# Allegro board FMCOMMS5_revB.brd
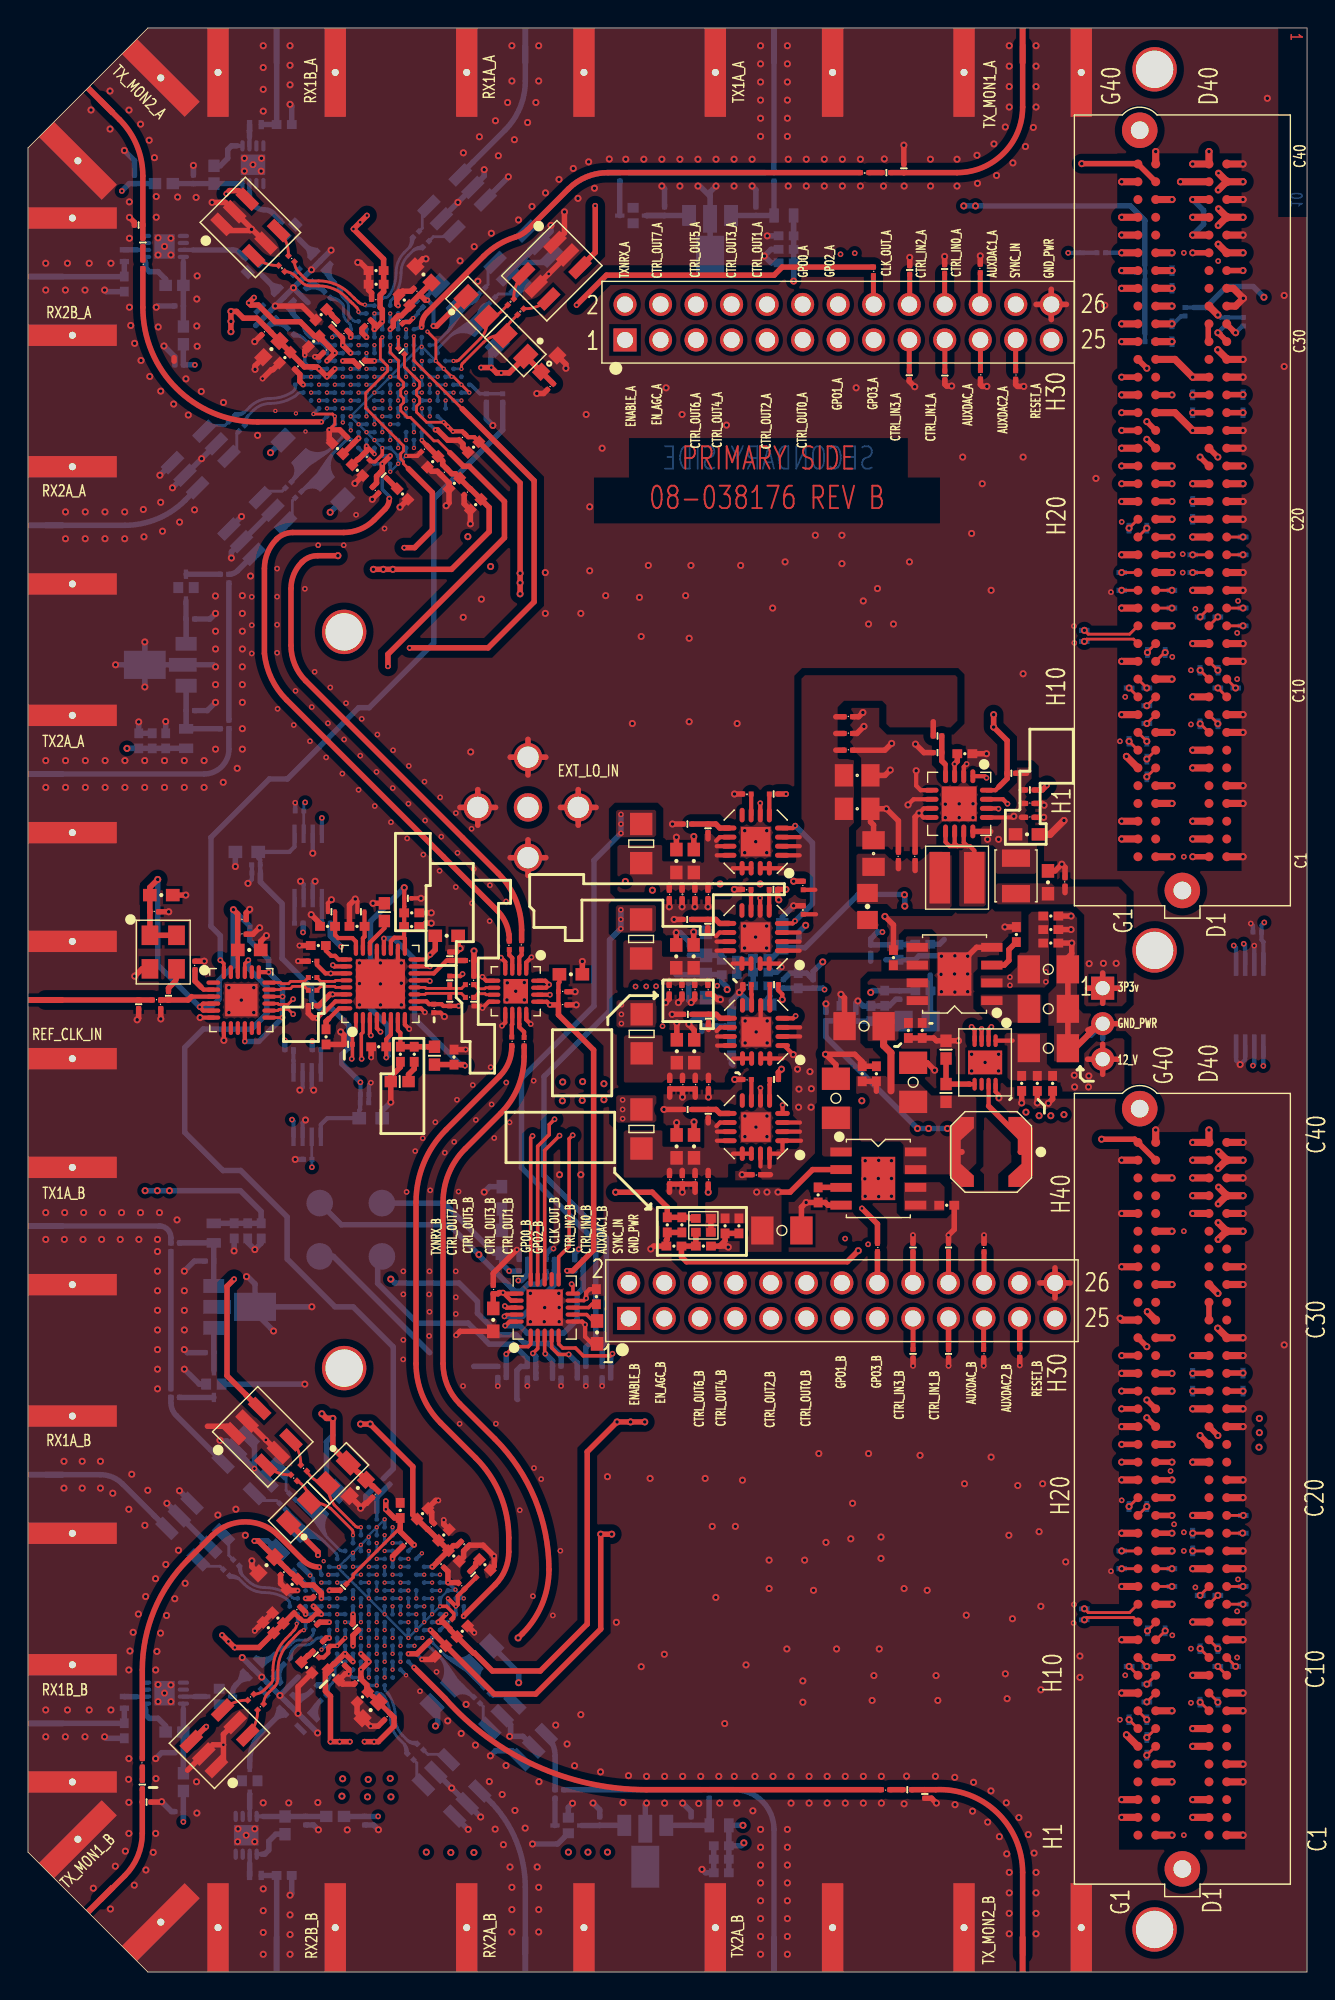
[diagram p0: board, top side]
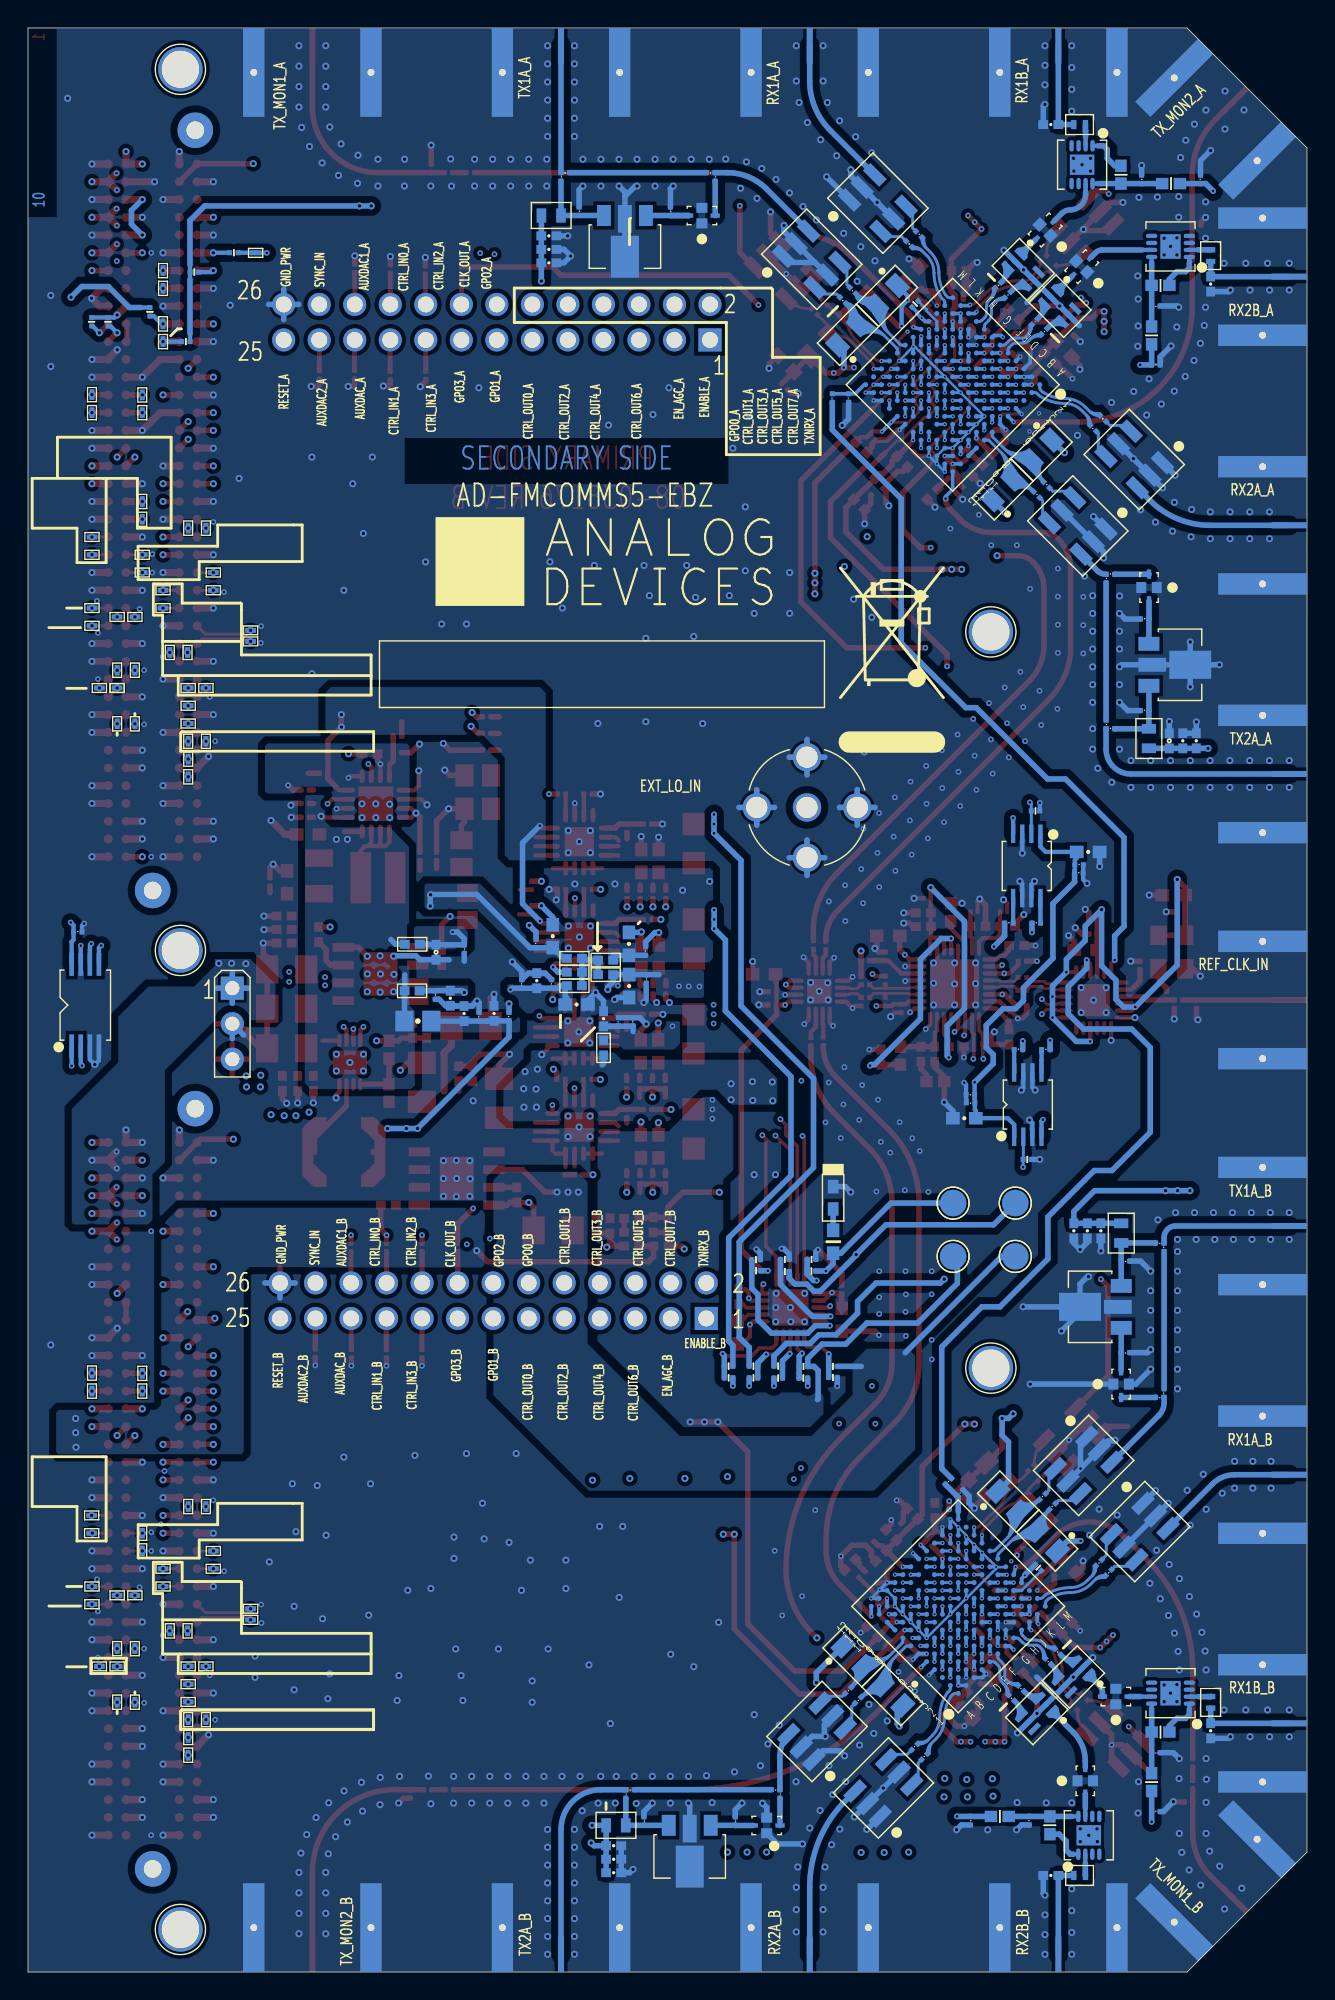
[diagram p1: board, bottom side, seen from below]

Outline 91.45 x 139 mm; copper layers: TOP, L2_GND, L3_PWR, L4_GND, L5_SIG, L6_SIG, L7_GND, L8_PWR, L9_GND, BOTTOM. Coordinates in mm from the lower left corner of the outline.
Outline path: 0,130.42 0,8.57 8.57,0 91.45,0 91.45,139 8.57,139 0,130.42

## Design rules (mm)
net group DIFFPAIR15: nets RX_D5_N_A RX_D5_P_A
net group DIFFPAIR16: nets RX_D2_N_A RX_D2_P_A
net group DIFFPAIR17: nets RX_D0_N_A RX_D0_P_A
net group DIFFPAIR18: nets DATA_CLK_N_A DATA_CLK_P_A
net group DIFFPAIR19: nets RX_D1_N_A RX_D1_P_A
net group DIFFPAIR20: nets RX_FRAME_N_A RX_FRAME_P_A
net group DIFFPAIR21: nets RX_D3_N_A RX_D3_P_A
net group DIFFPAIR22: nets RX_D4_N_A RX_D4_P_A
net group DIFFPAIR23: nets RX_D5_N_B RX_D5_P_B
net group DIFFPAIR24: nets RX_D2_N_B RX_D2_P_B
net group DIFFPAIR25: nets RX_D0_N_B RX_D0_P_B
net group DIFFPAIR26: nets DATA_CLK_N_B DATA_CLK_P_B
net group DIFFPAIR27: nets RX_D1_N_B RX_D1_P_B
net group DIFFPAIR28: nets RX_FRAME_N_B RX_FRAME_P_B
net group DIFFPAIR29: nets RX_D3_N_B RX_D3_P_B
net group DIFFPAIR30: nets RX_D4_N_B RX_D4_P_B
net group DIFFPAIR31: nets FB_CLK_N_A FB_CLK_P_A
net group DIFFPAIR32: nets TX_D4_N_A TX_D4_P_A
net group DIFFPAIR33: nets TX_D0_N_A TX_D0_P_A
net group DIFFPAIR34: nets TX_D2_N_A TX_D2_P_A
net group DIFFPAIR35: nets TX_FRAME_N_A TX_FRAME_P_A
net group DIFFPAIR36: nets TX_D3_N_A TX_D3_P_A
net group DIFFPAIR37: nets TX_D1_N_A TX_D1_P_A
net group DIFFPAIR38: nets TX_D5_N_A TX_D5_P_A
net group DIFFPAIR39: nets TX_D5_N_B TX_D5_P_B
net group DIFFPAIR40: nets TX_D1_N_B TX_D1_P_B
net group DIFFPAIR41: nets TX_D2_N_B TX_D2_P_B
net group DIFFPAIR42: nets FB_CLK_N_B FB_CLK_P_B
net group DIFFPAIR43: nets TX_D3_N_B TX_D3_P_B
net group DIFFPAIR44: nets TX_FRAME_N_B TX_FRAME_P_B
net group DIFFPAIR45: nets TX_D4_N_B TX_D4_P_B
net group DIFFPAIR46: nets TX_D0_N_B TX_D0_P_B
net group DIFFPAIR47: nets REF_CLK_FMC_N REF_CLK_FMC_P
net group DIFFPAIR48: nets CAL_SW_1 CAL_SW_2
net group DIFFPAIR49: nets 5355_REF_N 5355_REF_P
net group DIFFPAIR50: nets UNNAMED_5_ADCLK846_I21_OUT2 UNNAMED_5_ADCLK846_I21_OUT2N
net group DIFFPAIR51: nets TX1B_N_A TX1B_P_A
net group DIFFPAIR52: nets RX1C_N_A RX1C_P_A
net group DIFFPAIR53: nets TX2A_N_B TX2A_P_B
net group DIFFPAIR54: nets RX2A_N_B RX2A_P_B
net group DIFFPAIR55: nets TX1A_N_B TX1A_P_B
net group DIFFPAIR56: nets RX1A_N_B RX1A_P_B
net group DIFFPAIR57: nets RX2B_N_A RX2B_P_A
net group DIFFPAIR58: nets RX1B_N_A RX1B_P_A
net group DIFFPAIR59: nets RX1B_N_B RX1B_P_B
net group DIFFPAIR60: nets RX2B_N_B RX2B_P_B
net group DIFFPAIR61: nets TX1B_N_B TX1B_P_B
net group DIFFPAIR62: nets RX1C_N_B RX1C_P_B
net group DIFFPAIR63: nets 13617_IN_N 13617_IN_P
net group DIFFPAIR64: nets 5355_RFOUT_N 5355_RFOUT_P
net group SINGLE-ENDED: nets RX1A_N_A RX1A_P_A RX2A_N_A RX2A_P_A SYNC_IN TX1A_N_A TX1A_P_A TX2A_N_A TX2A_P_A

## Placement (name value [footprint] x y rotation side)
C101  1000pF  [C0201]  59.82 128.66 180 top
C102  1000pF  [C0201]  8.21 122.11 270 top
C103  1uF  [C0402]  7.92 88.03 90 bottom
C104  1000pF  [C0201]  24.85 105.96 135 top
C105  1uF  [C0402]  26.78 105.68 315 top
C106  18pF  [C0201]  28.45 123.54 225 bottom
C107  18pF  [C0201]  27.75 124.24 225 bottom
C108  18pF  [C0201]  14.59 111.08 45 bottom
C109  18pF  [C0201]  15.29 110.38 45 bottom
C110  18pF  [C0201]  14.37 99.63 270 bottom
C111  18pF  [C0201]  14.37 89.2 270 bottom
C112  1200pF  [C0402]  9.85 88.03 270 bottom
C113  68pF  [C0402]  8.88 88.03 270 bottom
C114  18pF  [C0201]  11.61 96.74 180 bottom
C115  18pF  [C0201]  11.61 90.19 180 bottom
C116  1000pF  [C0201]  22.61 117.13 45 top
C117  1uF  [C0402]  20.96 118.5 225 top
C118  1000pF  [C0201]  37.35 113.35 45 top
C119  10UF  [C0603]  37.27 115 45 top
C120  1000pF  [C0201]  16.92 117.26 45 top
C121  10UF  [C0603]  17.41 116.04 225 top
C122  18pF  [C0201]  33.18 119.53 45 bottom
C123  18pF  [C0201]  32.48 120.23 45 bottom
C124  18pF  [C0201]  18.63 106.33 225 bottom
C125  18pF  [C0201]  19.33 105.63 225 bottom
C126  18pF  [C0201]  18.84 122.5 315 top
C127  18pF  [C0201]  18.14 121.8 315 top
C128  18pF  [C0201]  22.08 120.61 315 bottom
C129  18pF  [C0201]  21.4 119.93 315 bottom
C130  18pF  [C0201]  19.47 118 315 bottom
C131  18pF  [C0201]  18.78 117.31 315 bottom
C132  18pF  [C0201]  34.52 119.41 45 top
C133  18pF  [C0201]  35.22 118.71 45 top
C134  1000pF  [C0201]  27.8 120.15 315 top
C135  10UF  [C0603]  28.28 121.37 135 top
C136  18pF  [C0201]  42.63 128.66 0 bottom
C137  18pF  [C0201]  53.04 128.66 0 bottom
C138  0.1uF  [C0201]  42.32 128.35 270 bottom
C139  0.1uF  [C0201]  53.34 128.35 270 bottom
C140  0.1uF  [C0201]  14.06 99.93 180 bottom
C142  0.1uF  [C0201]  60.45 121.6 270 top
C143  0.1uF  [C0201]  68.1 114.2 270 top
C144  0.1uF  [C0201]  68.09 121.81 90 top
C145  0.1uF  [C0201]  70.62 114.19 270 top
C146  0.75pF  [C0402]  18.32 132.09 180 bottom
C147  1000pF  [C0201]  11.83 128.18 270 bottom
C148  0.1uF  [C0201]  7.62 128.18 90 bottom
C149  1000pF  [C0201]  10.81 119.12 0 bottom
C150  0.1uF  [C0201]  10.81 114.91 180 bottom
C151  0.75pF  [C0402]  6.89 120.69 90 bottom
C152  1uF  [C0402]  54.21 124.14 180 bottom
C153  1200pF  [C0402]  54.21 122.2 0 bottom
C154  68pF  [C0402]  54.21 123.17 0 bottom
C155  18pF  [C0201]  52.05 125.9 270 bottom
C156  18pF  [C0201]  45.52 125.9 270 bottom
C162  0.1uF  [C0201]  14.06 88.9 180 bottom
C165  39pF  [C0201]  33.94 112.54 90 bottom
C166  18pF  [C0201]  32.78 112.54 90 bottom
C201  1000pF  [C0201]  8.17 14.96 90 top
C202  1000pF  [C0201]  61.32 13.04 180 top
C203  1uF  [C0402]  49.57 8.07 180 bottom
C204  1000pF  [C0201]  31 27.6 315 top
C205  1uF  [C0402]  32.67 29.12 315 top
C206  18pF  [C0201]  27.35 15.4 135 bottom
C207  18pF  [C0201]  28.05 16.1 135 bottom
C208  18pF  [C0201]  14.89 29.26 315 bottom
C209  18pF  [C0201]  14.19 28.56 315 bottom
C210  18pF  [C0201]  37.99 13.04 0 bottom
C211  18pF  [C0201]  48.4 13.04 0 bottom
C212  1200pF  [C0402]  49.57 7.1 0 bottom
C213  68pF  [C0402]  49.57 9.03 0 bottom
C214  18pF  [C0201]  40.89 10.79 270 bottom
C215  18pF  [C0201]  47.41 10.79 270 bottom
C216  1000pF  [C0201]  21.3 23.42 135 top
C217  1uF  [C0402]  19.93 21.77 315 top
C218  1000pF  [C0201]  24.84 34.14 45 top
C219  10UF  [C0603]  23.59 34.61 225 top
C220  1000pF  [C0201]  25.69 18.24 45 top
C221  10UF  [C0603]  24.5 18.73 225 top
C222  18pF  [C0201]  18.91 33.99 135 bottom
C223  18pF  [C0201]  18.2 33.29 135 bottom
C224  18pF  [C0201]  32.1 19.44 315 bottom
C225  18pF  [C0201]  32.8 20.14 315 bottom
C226  18pF  [C0201]  15.93 19.65 45 top
C227  18pF  [C0201]  16.63 18.95 45 top
C228  18pF  [C0201]  17.82 22.89 45 bottom
C229  18pF  [C0201]  18.5 22.21 45 bottom
C230  18pF  [C0201]  20.44 20.28 45 bottom
C231  18pF  [C0201]  21.12 19.6 45 bottom
C232  18pF  [C0201]  19.02 35.33 135 top
C233  18pF  [C0201]  19.72 36.03 135 top
C234  1000pF  [C0201]  28.82 31.86 225 top
C235  10UF  [C0603]  17.06 29.09 225 top
C236  18pF  [C0201]  10.22 41.4 90 bottom
C237  18pF  [C0201]  10.22 51.82 90 bottom
C238  0.1uF  [C0201]  10.53 41.09 0 bottom
C239  0.1uF  [C0201]  10.53 52.13 0 bottom
C240  0.1uF  [C0201]  37.69 12.73 270 bottom
C242  0.1uF  [C0201]  60.74 51.8 270 top
C243  0.1uF  [C0201]  68.33 44.21 270 top
C244  0.1uF  [C0201]  68.36 51.8 90 top
C245  0.1uF  [C0201]  70.91 44.25 270 top
C246  0.75pF  [C0402]  6.89 17.25 90 bottom
C247  1000pF  [C0201]  10.81 15.68 0 bottom
C248  0.1uF  [C0201]  10.81 11.47 180 bottom
C249  1000pF  [C0201]  19.86 10.82 90 bottom
C250  0.1uF  [C0201]  24.07 10.82 270 bottom
C251  0.75pF  [C0402]  18.32 6.91 180 bottom
C252  1uF  [C0402]  15.71 52.99 270 bottom
C253  1200pF  [C0402]  16.67 52.99 90 bottom
C254  68pF  [C0402]  14.74 52.99 90 bottom
C255  18pF  [C0201]  12.98 50.83 0 bottom
C256  18pF  [C0201]  12.98 44.29 0 bottom
C262  0.1uF  [C0201]  48.71 12.73 270 bottom
C265  39pF  [C0201]  25.65 35.09 315 bottom
C266  18pF  [C0201]  24.82 34.26 315 bottom
C301  0.1uF  [C0201]  9.19 69.5 0 top
C302  0.01UF  [C0201]  11.94 71.97 90 top
C303  10UF  [C0603]  15.82 73.08 0 top
C304  0.1uF  [C0201]  15.3 74.21 0 top
C305  0.1uF  [C0201]  15.3 75.25 0 top
C306  10UF  [C0603]  29.94 74.09 0 top
C307  0.1uF  [C0201]  20.35 72.28 180 top
C308  0.1uF  [C0201]  29.01 68.9 270 top
C309  0.1UF  [C0402]  27.43 74.75 180 top
C310  0.1uF  [C0201]  87.89 74.36 180 bottom
C311  0.1uF  [C0201]  33.27 48.8 270 top
C312  10UF  [C0603]  33.27 46.63 270 top
C313  1uF  [C0402]  40.64 48.29 90 top
C314  10UF  [C0603]  40.69 45.73 270 top
C317  1uF  [C0402]  25.08 66.15 0 top
C318  0.01UF  [C0201]  20.35 71.11 0 top
C319  0.01UF  [C0201]  20.35 70.19 0 top
C320  0.1UF  [C0402]  27.44 75.73 180 top
C321  0.1UF  [C0402]  23.53 74.76 0 top
C322  0.1UF  [C0402]  21.42 74.76 0 top
C323  10pF  [C0201-2]  27.16 76.77 180 top
C324  10pF  [C0201-2]  23.81 75.81 0 top
C325  10pF  [C0201-2]  21.7 75.81 0 top
C326  0.1UF  [C0402]  21.31 66.86 90 top
C327  0.1UF  [C0402]  20.76 73.39 0 top
C328  2700PF  [C0402]  26.63 65.62 90 top
C329  39000pF  [C0402]  27.62 65.62 90 top
C330  1200pF  [C0402]  30.46 65.42 270 top
C331  18pF  [C0201]  31.58 69.68 0 top
C332  18pF  [C0201]  31.58 70.6 0 top
C333  10UF  [C0603]  38.82 71.34 0 top
C334  0.1uF  [C0201]  38.23 70.09 0 top
C335  0.1uF  [C0201]  38.23 69.15 0 top
C336  18pF  [C0201]  35.3 73.44 90 top
C337  18pF  [C0201]  34.41 73.41 90 top
C338  18pF  [C0201]  35.47 66.51 270 top
C339  18pF  [C0201]  34.59 66.55 270 top
C340  10UF  [C0603]  15.65 80.09 180 bottom
C341  0.1uF  [C0201]  16.3 79.17 180 bottom
C342  0.1uF  [C0201]  16.31 78.58 180 bottom
C343  10UF  [C0603]  24.5 61.05 0 bottom
C344  0.1uF  [C0201]  24.07 62.75 0 bottom
C345  0.1uF  [C0201]  24.06 62.15 0 bottom
C346  10UF  [C0603]  9.53 77 0 top
C347  0.1uF  [C0201]  9.02 75.81 0 top
C348  18pF  [C0201]  9.5 69.19 90 top
C349  18pF  [C0201]  19.36 74.99 180 bottom
C350  18pF  [C0201]  21.32 74.99 180 bottom
C351  18pF  [C0201]  20.63 65.95 180 bottom
C352  18pF  [C0201]  18.68 65.95 180 bottom
C353  18pF  [C0201]  31.59 72.32 180 top
C390  18pF  [C0201]  31.88 70.9 90 top
C501  0.1uF  [C0201]  74.15 77.94 90 top
C502  10UF  [C0603]  72.93 77.91 90 top
C503  10UF  [C0603]  71.43 81.34 0 top
C504  0.1uF  [C0201]  71.64 82.56 0 top
C505  0.1uF  [C0201]  71.64 83.55 0 top
C510  1uF  [C0402]  58.13 68.54 90 bottom
C511  0.01UF  [C0201]  57.06 68.31 90 bottom
C512  0.01UF  [C0201]  59.2 68.3 90 bottom
C513  1uF  [C0402]  60.27 68.53 90 bottom
C514  0.1uF  [C0201]  46.78 56.64 270 top
C515  0.01UF  [C0201]  22.44 22.13 315 top
C516  1uF  [C0402]  21.83 21.24 315 top
C517  1uF  [C0402]  17.18 24.62 135 top
C518  1uF  [C0402]  62.28 72.92 270 bottom
C519  0.01UF  [C0201]  60.26 73.14 270 bottom
C520  0.01UF  [C0201]  23.05 109.51 135 top
C521  1uF  [C0402]  22.13 108.93 135 top
C522  1uF  [C0402]  61.26 69.63 270 bottom
C523  0.01UF  [C0201]  62.33 69.86 270 bottom
C524  0.01UF  [C0201]  28.92 23.86 225 top
C525  1uF  [C0402]  29.5 22.94 225 top
C530  10uF  [C1206H71]  72.96 66.05 180 top
C531  0.1UF  [C0402]  71.05 63.54 90 top
C532  0.1UF  [C0402]  72.17 63.54 90 top
C533  0.1UF  [C0402]  73.26 63.54 90 top
C534  10uF  [C1206H71]  63.29 63.61 270 top
C535  0.1UF  [C0402]  60.66 64.22 270 top
C536  0.1UF  [C0402]  59.65 64.22 270 top
C537  10uF  [C1206H71]  57.77 62.47 90 top
C538  1uF  [C0402]  56.5 55.56 90 top
C539  1uF  [C0402]  65.69 54.83 180 top
C540  10uF  [C1206H71]  53.91 53.02 180 top
C541  0.1UF  [C0402]  49.84 53.35 90 top
C542  0.1UF  [C0402]  50.83 53.35 90 top
C543  0.1UF  [C0402]  46.75 53.42 90 top
C544  1uF  [C0402]  45.71 53.42 90 top
C545  0.01UF  [C0201]  30.11 25.03 45 top
C546  1uF  [C0402]  17.87 25.31 135 top
C547  0.1UF  [C0402]  48.29 51.9 180 top
C548  1uF  [C0402]  46.18 51.9 0 top
C549  1uF  [C0402]  66.99 87.11 0 top
C550  47uF  [C0805H60]  60.46 79.97 270 top
C551  0.1uF  [C0201]  63.43 79.77 90 top
C552  0.1uF  [C0201]  62.24 79.77 90 top
C553  47uF  [C0805H60]  59.29 83.17 180 top
C554  47uF  [C0805H60]  59.29 85.56 180 top
C555  0.1uF  [C0201]  58.66 87.36 0 top
C556  0.1uF  [C0201]  58.66 88.56 0 top
C557  0.01UF  [C0201]  48.19 67.93 90 bottom
C558  0.01UF  [C0201]  49.23 67.93 90 bottom
C559  1uF  [C0402]  50.3 68.16 90 bottom
C560  0.1uF  [C0201]  58.66 89.75 0 top
C561  0.01UF  [C0201]  51.4 84.23 180 top
C562  10UF  [C0603]  47.61 79.44 90 top
C563  10UF  [C0603]  46.36 79.44 90 top
C564  0.1uF  [C0201]  46.77 77.05 270 top
C565  0.1uF  [C0201]  45.85 77.05 270 top
C566  0.1uF  [C0201]  47.68 77.05 270 top
C567  0.1uF  [C0201]  48.62 77.05 270 top
C568  1uF  [C0402]  23.55 107.38 315 top
C569  0.01UF  [C0201]  24.21 108.32 315 top
C570  0.01UF  [C0201]  21.32 115.99 225 top
C571  1uF  [C0402]  20.43 116.6 225 top
C572  0.01UF  [C0201]  24.87 119.6 180 top
C573  1uF  [C0402]  24.89 121.65 180 top
C574  1uF  [C0402]  24.89 120.68 180 top
C575  0.01UF  [C0201]  24.29 117.89 225 top
C576  0.1uF  [C0201]  55.43 75.93 90 top
C577  0.01UF  [C0201]  51.39 77.41 180 top
C578  10UF  [C0603]  46.35 72.62 90 top
C579  10UF  [C0603]  47.6 72.62 90 top
C580  0.1uF  [C0201]  46.76 70.23 270 top
C581  0.1uF  [C0201]  48.61 70.23 270 top
C582  0.1uF  [C0201]  47.67 70.23 270 top
C583  0.1uF  [C0201]  45.84 70.23 270 top
C584  1uF  [C0402]  26.91 119.55 135 top
C585  0.01UF  [C0201]  26.55 118.07 315 top
C586  0.01UF  [C0201]  31.4 105.83 225 top
C587  1uF  [C0402]  32.01 104.91 225 top
C588  1uF  [C0402]  28.94 107.99 225 top
C589  0.01UF  [C0201]  28.33 108.9 225 top
C590  0.01UF  [C0201]  29.75 107.25 225 top
C591  1uF  [C0402]  30.49 106.44 225 top
C592  1uF  [C0402]  18.37 115.43 225 top
C593  0.01UF  [C0201]  19.29 114.82 225 top
C594  0.1uF  [C0201]  52.08 57.01 180 top
C595  0.01UF  [C0201]  51.42 63.82 180 top
C596  10UF  [C0603]  46.38 59.03 90 top
C597  10UF  [C0603]  47.62 59.03 90 top
C598  0.1uF  [C0201]  48.64 56.64 270 top
C599  0.1uF  [C0201]  47.7 56.64 270 top
C607  0.01UF  [C0201]  20.46 25.05 315 top
C608  0.01UF  [C0201]  19.24 25.89 45 top
C609  1uF  [C0402]  31.05 24.36 45 top
C610  10UF  [C0603]  48.49 73.51 90 bottom
C611  0.1uF  [C0201]  47.29 73 90 bottom
C612  1uF  [C0402]  31.86 109.03 225 top
C613  0.01UF  [C0201]  31.05 109.74 225 top
C614  10UF  [C0603]  48.47 70.5 270 bottom
C615  0.1uF  [C0201]  47.25 71.01 270 bottom
C616  1uF  [C0402]  26.62 33.01 90 top
C617  0.01UF  [C0201]  27.01 30.66 225 top
C618  10UF  [C0603]  53.93 74.06 90 bottom
C619  0.1uF  [C0201]  55.13 73.55 90 bottom
C620  0.1uF  [C0201]  55.43 77.69 90 top
C621  0.01UF  [C0201]  51.42 70.6 180 top
C622  10UF  [C0603]  47.64 65.83 90 top
C623  10UF  [C0603]  46.39 65.83 90 top
C624  0.1uF  [C0201]  47.71 63.45 270 top
C625  0.1uF  [C0201]  48.65 63.45 270 top
C626  0.1uF  [C0201]  46.8 63.45 270 top
C627  0.1uF  [C0201]  45.89 63.45 270 top
C628  0.01UF  [C0201]  23.58 20.86 225 top
C629  1uF  [C0402]  29.73 31.25 45 top
C630  0.01UF  [C0201]  20.61 27.03 225 top
C631  1uF  [C0402]  23.92 19.67 225 top
C632  0.01UF  [C0201]  31.18 30.56 315 top
C633  1uF  [C0402]  18.89 27.72 225 top
C634  0.01UF  [C0201]  29.53 29.14 315 top
C635  1uF  [C0402]  30.44 29.75 315 top
C636  1uF  [C0402]  28.21 32.77 45 top
C637  0.01UF  [C0201]  18.28 28.61 225 top
C638  10UF  [C0603]  52.23 69.18 180 bottom
C639  0.1uF  [C0201]  54.01 70.65 90 bottom
C640  1uF  [C0402]  55.07 70.88 90 bottom
C641  0.01UF  [C0201]  56.14 70.65 90 bottom
C642  10uF  [C1206H71]  72.96 68.87 0 top
C643  1uF  [C0402]  70.67 74.18 270 top
C644  10uF  [C1206H71]  59.78 67.63 0 top
C645  0.1UF  [C0402]  63.94 67.32 90 top
C646  0.1UF  [C0402]  62.95 67.32 90 top
C647  1uF  [C0402]  61.88 72.53 270 top
C648  10uF  [C1206H71]  72.96 71.69 180 top
C649  0.1UF  [C0402]  73.13 73.57 180 top
C650  0.1uF  [C0201]  45.87 56.64 270 top
C651  0.1UF  [C0402]  73.13 74.54 180 top
C688  0.1UF  [C0402]  73.13 75.5 180 top
CAL_SW_1  TP-108  [TPSM70X135]  83.28 111.49 180 bottom
CAL_SW_2  TP-108  [TPSM70X135]  83.28 112.76 180 bottom
CAL_SW_3  TP-108  [TPSM70X135]  83.28 41.54 180 bottom
CAL_SW_4  TP-108  [TPSM70X135]  83.28 42.81 180 bottom
DATA_CLK_N_A  TP-108  [TPSM70X135]  80 86.73 180 bottom
DATA_CLK_N_B  TP-108  [TPSM70X135]  80 16.77 180 bottom
DATA_CLK_P_A  TP-108  [TPSM70X135]  80 85.46 180 bottom
DATA_CLK_P_B  TP-108  [TPSM70X135]  80 15.5 180 bottom
DEBUG_1  TP-108  [TPSM70X135]  86.88 111.49 180 bottom
DEBUG_2  TP-108  [TPSM70X135]  86.88 112.78 180 bottom
DEBUG_3  TP-108  [TPSM70X135]  86.88 41.54 180 bottom
DEBUG_4  TP-108  [TPSM70X135]  86.88 42.83 180 bottom
DS301  LTST-C190GKT  [LED0603]  33.88 55.36 270 bottom
E1  75OHM  [L0402]  52.38 70.52 0 bottom
E501  75OHM  [L0402]  63.98 73.48 180 bottom
E503  75OHM  [L0402]  63.99 70.16 180 bottom
E504  39OHM  [L0805]  63.57 67.99 0 bottom
E507  75OHM  [L0402]  48.29 53.89 180 top
E509  75OHM  [L0402]  48.29 52.9 180 top
E510  39OHM  [L0805]  60.03 76.19 270 top
E511  75OHM  [L0402]  50.3 66.08 90 bottom
E512  75OHM  [L0402]  50.15 72.35 180 bottom
E513  75OHM  [L0402]  52.38 71.49 180 bottom
E514  75OHM  [L0402]  50.15 71.31 180 bottom
E515  75OHM  [L0402]  52.38 72.48 180 bottom
FB_CLK_N_A  TP-108  [TPSM70X135]  80.04 94.35 180 bottom
FB_CLK_N_B  TP-108  [TPSM70X135]  80.04 24.39 180 bottom
FB_CLK_P_A  TP-108  [TPSM70X135]  81.31 94.35 180 bottom
FB_CLK_P_B  TP-108  [TPSM70X135]  81.31 24.39 0 bottom
FL100  2400-2500MEGHZ  [FL0603]  18.72 124.55 135 bottom
FL101  2400-2500MEGHZ  [FL0603]  16.11 121.94 135 bottom
FL102  2400-2500MEGHZ  [FL0603]  43.27 125.58 180 bottom
FL103  2400-2500MEGHZ  [FL0603]  11.3 98.99 90 bottom
FL200  2400-2500MEGHZ  [FL0603]  13.67 19.7 180 bottom
FL201  2400-2500MEGHZ  [FL0603]  15.86 13.67 270 bottom
FL202  2400-2500MEGHZ  [FL0603]  13.29 42.04 270 bottom
FL203  2400-2500MEGHZ  [FL0603]  38.63 10.48 180 bottom
J101  JOHNSON142-0701-851  [CNJOHNSON142-0701-851]  71.12 138.24 90 top
J102  JOHNSON142-0701-851  [CNJOHNSON142-0701-851]  4.83 134.17 135 top
J103  JOHNSON142-0701-851  [CNJOHNSON142-0701-851]  17.78 138.24 90 bottom
J104  JOHNSON142-0701-851  [CNJOHNSON142-0701-851]  0.76 121.22 180 bottom
J110  JOHNSON142-0701-851  [CNJOHNSON142-0701-851]  0.76 103.44 180 bottom
J111  JOHNSON142-0701-851  [CNJOHNSON142-0701-851]  35.56 138.24 90 bottom
J112  JOHNSON142-0701-851  [CNJOHNSON142-0701-851]  53.34 138.24 90 bottom
J113  JOHNSON142-0701-851  [CNJOHNSON142-0701-851]  0.76 85.66 180 bottom
J201  JOHNSON142-0701-851  [CNJOHNSON142-0701-851]  4.83 4.83 225 top
J202  JOHNSON142-0701-851  [CNJOHNSON142-0701-851]  71.12 0.76 270 top
J203  JOHNSON142-0701-851  [CNJOHNSON142-0701-851]  0.76 17.78 180 bottom
J204  JOHNSON142-0701-851  [CNJOHNSON142-0701-851]  17.78 0.76 270 bottom
J210  JOHNSON142-0701-851  [CNJOHNSON142-0701-851]  0.76 35.56 180 bottom
J211  JOHNSON142-0701-851  [CNJOHNSON142-0701-851]  35.56 0.76 270 bottom
J212  JOHNSON142-0701-851  [CNJOHNSON142-0701-851]  0.76 53.34 180 bottom
J213  JOHNSON142-0701-851  [CNJOHNSON142-0701-851]  53.34 0.76 270 bottom
J301  JOHNSON142-0701-851  [CNJOHNSON142-0701-851]  0.76 69.5 180 top
J302  142-0701-201  [CNJOHNSON142-0701-201]  35.75 83.27 135 bottom
L101  330nH  [L0805-F]  32.82 117.06 135 bottom
L102  330nH  [L0805-F]  34.85 116.26 135 top
L103  330nH  [L0805-F]  30.04 119.85 315 bottom
L104  330nH  [L0805-F]  32.07 119.05 315 top
L105  330nH  [L0805-F]  18.98 108.79 315 bottom
L106  1nH  [L0402-2]  16.26 132.09 180 bottom
L107  330nH  [L0805-F]  21.77 106.01 135 bottom
L108  1nH  [L0402-2]  6.89 122.72 90 bottom
L110  43nH  [L7144A]  54.04 125.59 0 bottom
L111  43nH  [L7144A]  11.31 88.19 270 bottom
L201  330nH  [L0805-F]  21.37 33.63 225 bottom
L202  330nH  [L0805-F]  22.17 35.66 225 top
L203  330nH  [L0805-F]  18.58 30.85 45 bottom
L204  330nH  [L0805-F]  19.38 32.88 45 top
L205  330nH  [L0805-F]  29.64 19.79 45 bottom
L206  1nH  [L0402-2]  6.89 19.28 90 bottom
L207  330nH  [L0805-F]  32.42 22.58 225 bottom
L208  1nH  [L0402-2]  16.26 6.91 180 bottom
L210  43nH  [L7144A]  13.28 52.83 90 bottom
L211  43nH  [L7144A]  49.41 10.49 0 bottom
L501  0.47uH  [L1210H67]  70.65 78.37 90 top
L502  22uH  [LSMSQ189H123]  68.87 58.64 180 top
L503  2.2uH  [LSMSQ157H83]  66.43 78.24 180 top
NOREF  -  []  200.85 204.42 0 top
NOREF#2  -  []  -116.36 -148.73 0 top
NOREF#3  -  []  0 8.57 315 top
NOREF#4  -  []  8.57 139 0 top
NOREF#5  -  []  49.5 145.34 0 top
NOREF#6  -  []  82.54 7.37 0 top
NOREF#7  -  []  83.81 7.37 0 top
NOREF#8  -  []  -116.87 -148.73 0 top
NOREF#9  -  []  91.45 0 90 top
NOREF#10  -  []  62.31 97.68 0 top
NOREF#11  -  []  52.94 107.51 0 top
NOREF#12  -  []  -116.87 -148.73 0 top
NOREF#13  -  []  -91.79 197.12 0 top
NOREF#14  VAL  [unnamed#2]  80.55 3.04 180 bottom
NOREF#15  -  []  20.41 104.07 180 bottom
NOREF#16  VAL  [unnamed#2]  22.61 95.82 180 bottom
NOREF#17  VAL  [unnamed#2]  80.55 73.04 180 bottom
NOREF#18  VAL  [unnamed#2]  22.61 43.18 180 bottom
NOREF#19  VAL  [unnamed#2]  80.55 136.04 180 bottom
P101  TSW-113-23-L-D  [CNSAMTECTSW-113-23-L-D-ST]  42.69 116.69 0 top
P201  TSW-113-23-L-D  [CNSAMTECTSW-113-23-L-D-ST]  42.95 46.73 0 top
P401  ASP-134604-01  [CNSAMTECASP-134604-01]  82.54 104.51 90 top
P402  ASP-134604-01  [CNSAMTECASP-134604-01]  82.54 34.55 90 top
P501  SAMTECTSW10608GS3PIN  [CNBERG1X3H205LD36]  76.84 70.35 270 bottom
R101  49.9  [R0201]  62.63 128.96 270 top
R102  49.9  [R0201]  7.91 124.91 0 top
R103  10K  [R0201]  26.7 115.89 135 top
R104  10K  [R0201]  63.01 114.17 270 top
R105  10K  [R0201]  63.05 121.7 90 top
R106  10K  [R0201]  65.56 114.15 270 top
R107  10K  [R0201]  65.54 121.77 90 top
R108  1.3K  [R0402]  13.3 128.51 270 bottom
R109  0  [R0402]  9.72 127.87 180 bottom
R110  1.3K  [R0402]  10.48 120.6 0 bottom
R111  10K  [R0201]  23.86 115.02 45 top
R112  0  [R0402]  11.11 117.02 270 bottom
R121  10  [R0201]  61.38 128.66 180 top
R122  10  [R0201]  8.21 123.66 270 top
R123  1  [R0201]  25.43 107.02 315 top
R124  1  [R0201]  21.9 117.84 45 top
R125  14.3K  [R0201]  28.02 119.27 315 bottom
R201  49.9  [R0201]  8.48 12.15 180 top
R202  49.9  [R0201]  64.13 12.73 90 top
R203  10K  [R0201]  22.54 27.51 225 top
R204  10K  [R0201]  63.28 44.2 270 top
R205  10K  [R0201]  63.28 51.8 90 top
R206  10K  [R0201]  65.82 44.2 270 top
R207  10K  [R0201]  65.82 51.8 90 top
R208  1.3K  [R0402]  10.48 17.16 0 bottom
R209  0  [R0402]  11.11 13.58 270 bottom
R210  1.3K  [R0402]  18.39 10.49 90 bottom
R211  10K  [R0201]  23.41 24.67 135 top
R212  0  [R0402]  21.96 11.13 0 bottom
R221  10  [R0201]  8.17 13.4 90 top
R222  10  [R0201]  62.88 13.04 180 top
R223  1  [R0201]  31.83 28.44 135 top
R224  1  [R0201]  20.59 22.71 135 top
R225  14.3K  [R0201]  19.21 28.92 45 bottom
R301  49.9  [R0201]  7.91 69.19 90 top
R302  237  [R0603]  33.88 52.21 270 bottom
R303  10K  [R0201]  39.4 50.14 0 bottom
R304  10K  [R0201]  37.34 50.09 0 bottom
R305  10K  [R0201]  35.44 50.12 0 bottom
R306  16K  [R0201]  39.4 50.93 0 bottom
R307  16K  [R0201]  37.34 50.95 0 bottom
R308  16K  [R0201]  35.43 50.95 0 bottom
R309  20K  [R0201]  33.9 43.3 0 bottom
R310  10K  [R0201]  36 43.3 0 bottom
R312  16K  [R0201]  33.9 42.51 0 bottom
R313  16K  [R0201]  36.01 42.47 0 bottom
R314  16K  [R0201]  37.81 42.47 180 bottom
R315  360  [R0402]  26.58 63.67 0 top
R316  680  [R0402]  29.07 65.52 90 top
R317  49.9  [R0201]  30.16 69.38 270 top
R318  49.9  [R0201]  30.16 70.9 90 top
R319  10K  [R0201]  19.41 83.02 180 bottom
R320  10K  [R0201]  20 58.1 180 bottom
R323  4.7K  [R0402]  25.48 75.78 270 top
R325  10K  [R0201]  41.36 43.32 0 bottom
R326  10K  [R0201]  39.58 43.32 180 bottom
R327  10K  [R0201]  37.81 43.33 180 bottom
R328  16K  [R0201]  39.58 42.48 180 bottom
R329  16K  [R0201]  41.36 42.48 0 bottom
R335  49.9  [R0201]  30.16 72.63 270 top
R350  49.9  [R0201]  31.88 69.38 90 top
R351  10K  [R0201]  20.35 69.09 180 top
R360  0  [R0201]  10.05 69.81 90 top
R401  2K  [R0201]  85.73 118 90 bottom
R402  2K  [R0201]  86.9 118 90 bottom
R403  10K  [R0201]  80.17 116.57 0 bottom
R404  49.9  [R0201]  76.74 122.93 180 bottom
R405  10K  [R0201]  82.74 118.71 270 bottom
R406  10K  [R0201]  22.89 66.33 180 top
R407  10K  [R0201]  79.56 121.54 180 bottom
R501  36K  [R0402]  65.64 65.95 270 top
R502  232K  [R0402]  65.64 62.85 270 top
R504  10K  [R0201]  70.31 85.71 0 top
R505  10K  [R0201]  65.03 87.19 0 top
R506  20K  [R0201]  65.03 88.38 180 top
R507  10K  [R0201]  53.31 84.23 0 top
R508  16K  [R0201]  48.62 81.78 270 top
R509  10K  [R0201]  47.15 82.08 0 top
R510  0  [R1206]  43.85 80.68 90 top
R511  10K  [R0201]  53.3 77.41 0 top
R512  16K  [R0201]  48.61 74.96 270 top
R513  10K  [R0201]  47.14 75.26 0 top
R514  0  [R1206]  43.84 73.86 90 top
R515  10K  [R0201]  53.35 63.82 0 top
R516  16K  [R0201]  48.64 61.37 270 top
R517  10K  [R0201]  47.17 61.67 0 top
R518  0  [R1206]  43.86 60.28 90 top
R519  10K  [R0201]  53.35 70.6 0 top
R520  16K  [R0201]  48.65 68.17 270 top
R521  10K  [R0201]  47.18 68.48 180 top
R522  0  [R1206]  43.88 67.08 270 top
R523  10  [R0201]  71.64 84.52 180 top
REF_CLK_FMC_N  TP-108  [TPSM70X135]  83.28 105.14 180 bottom
REF_CLK_FMC_P  TP-108  [TPSM70X135]  83.28 103.87 180 bottom
RX_D0_N_A  TP-108  [TPSM70X135]  80 88 180 bottom
RX_D0_N_B  TP-108  [TPSM70X135]  80 18.04 180 bottom
RX_D0_P_A  TP-108  [TPSM70X135]  78.73 88 180 bottom
RX_D0_P_B  TP-108  [TPSM70X135]  78.73 18.04 180 bottom
RX_D1_N_A  TP-108  [TPSM70X135]  80 90.54 90 bottom
RX_D1_N_B  TP-108  [TPSM70X135]  80 20.58 90 bottom
RX_D1_P_A  TP-108  [TPSM70X135]  80 89.27 90 bottom
RX_D1_P_B  TP-108  [TPSM70X135]  80 19.31 90 bottom
RX_D2_N_A  TP-108  [TPSM70X135]  80 91.81 270 bottom
RX_D2_N_B  TP-108  [TPSM70X135]  80 21.85 270 bottom
RX_D2_P_A  TP-108  [TPSM70X135]  78.73 91.81 270 bottom
RX_D2_P_B  TP-108  [TPSM70X135]  78.73 21.85 270 bottom
RX_D3_N_A  TP-108  [TPSM70X135]  85.08 93.08 180 bottom
RX_D3_N_B  TP-108  [TPSM70X135]  85.08 23.12 180 bottom
RX_D3_P_A  TP-108  [TPSM70X135]  83.81 93.08 180 bottom
RX_D3_P_B  TP-108  [TPSM70X135]  83.81 23.12 180 bottom
RX_D4_N_A  TP-108  [TPSM70X135]  86.35 91.81 270 bottom
RX_D4_N_B  TP-108  [TPSM70X135]  86.35 21.85 270 bottom
RX_D4_P_A  TP-108  [TPSM70X135]  85.08 91.81 270 bottom
RX_D4_P_B  TP-108  [TPSM70X135]  85.08 21.85 270 bottom
RX_D5_N_A  TP-108  [TPSM70X135]  75.53 95.93 90 bottom
RX_D5_N_B  TP-108  [TPSM70X135]  75.53 25.97 90 bottom
RX_D5_P_A  TP-108  [TPSM70X135]  75.53 95.14 270 bottom
RX_D5_P_B  TP-108  [TPSM70X135]  75.53 25.18 270 bottom
RX_FRAME_N_A  TP-108  [TPSM70X135]  85.08 89.25 180 bottom
RX_FRAME_N_B  TP-108  [TPSM70X135]  85.08 19.29 180 bottom
RX_FRAME_P_A  TP-108  [TPSM70X135]  83.81 89.25 180 bottom
RX_FRAME_P_B  TP-108  [TPSM70X135]  83.81 19.29 180 bottom
SPI_CLK  TP-108  [TPSM70X135]  75.18 122.92 90 bottom
SPI_DI  TP-108  [TPSM70X135]  81.8 120.38 180 bottom
SPI_DO  TP-108  [TPSM70X135]  81.8 121.65 180 bottom
SPI_ENB_A  TP-108  [TPSM70X135]  81.8 116.57 180 bottom
SPI_ENB_B  TP-108  [TPSM70X135]  81.8 117.84 180 bottom
T101  2450BL15B050E  [XFMR2450BL15B050]  20.29 121.72 315 bottom
T102  2450BL15B050E  [XFMR2450BL15B050]  17.67 119.11 315 bottom
T103  TCM1-63AX+  [TSML150W160H160]  15.9 124.74 45 top
T104  TCM1-63AX+  [TSML150W160H160]  37.46 121.64 315 top
T105  TCM1-63AX+  [TSML150W160H160]  12.35 108.14 315 bottom
T106  TCM1-63AX+  [TSML150W160H160]  30.68 126.48 135 bottom
T107  TCM1-63AX+  [TSML150W160H160]  35.41 122.46 135 bottom
T108  TCM1-63AX+  [TSML150W160H160]  16.39 103.39 315 bottom
T201  2450BL15B050E  [XFMR2450BL15B050]  16.71 21.1 45 bottom
T202  2450BL15B050E  [XFMR2450BL15B050]  19.32 18.48 45 bottom
T203  TCM1-63AX+  [TSML150W160H160]  13.69 16.71 135 top
T204  TCM1-63AX+  [TSML150W160H160]  16.79 38.27 45 top
T205  TCM1-63AX+  [TSML150W160H160]  11.96 31.5 225 bottom
T206  TCM1-63AX+  [TSML150W160H160]  30.29 13.16 45 bottom
T207  TCM1-63AX+  [TSML150W160H160]  15.97 36.22 225 bottom
T208  TCM1-63AX+  [TSML150W160H160]  35.04 17.2 45 bottom
TP302  WP45  [TPC75D45]  20.86 54.98 180 bottom
TP303  WP45  [TPC75D45]  25.31 54.98 180 bottom
TP306  WP45  [TPC75D45]  20.86 51.17 180 bottom
TP307  WP45  [TPC75D45]  25.31 51.17 180 bottom
TX_D0_N_A  TP-108  [TPSM70X135]  86.88 97.52 270 bottom
TX_D0_N_B  TP-108  [TPSM70X135]  86.88 27.57 90 bottom
TX_D0_P_A  TP-108  [TPSM70X135]  86.88 96.25 270 bottom
TX_D0_P_B  TP-108  [TPSM70X135]  86.88 26.3 270 bottom
TX_D1_N_A  TP-108  [TPSM70X135]  78.2 100.06 270 bottom
TX_D1_N_B  TP-108  [TPSM70X135]  78.2 30.11 90 bottom
TX_D1_P_A  TP-108  [TPSM70X135]  78.2 98.79 270 bottom
TX_D1_P_B  TP-108  [TPSM70X135]  78.2 28.84 90 bottom
TX_D2_N_A  TP-108  [TPSM70X135]  81.8 98.79 270 bottom
TX_D2_N_B  TP-108  [TPSM70X135]  81.8 28.84 90 bottom
TX_D2_P_A  TP-108  [TPSM70X135]  81.8 97.52 270 bottom
TX_D2_P_B  TP-108  [TPSM70X135]  81.8 27.57 270 bottom
TX_D3_N_A  TP-108  [TPSM70X135]  83.28 101.33 270 bottom
TX_D3_N_B  TP-108  [TPSM70X135]  83.28 31.38 0 bottom
TX_D3_P_A  TP-108  [TPSM70X135]  83.28 100.06 270 bottom
TX_D3_P_B  TP-108  [TPSM70X135]  83.28 30.11 0 bottom
TX_D4_N_A  TP-108  [TPSM70X135]  86.88 102.6 270 bottom
TX_D4_N_B  TP-108  [TPSM70X135]  86.9 32.65 270 bottom
TX_D4_P_A  TP-108  [TPSM70X135]  86.88 101.33 270 bottom
TX_D4_P_B  TP-108  [TPSM70X135]  86.9 31.38 270 bottom
TX_D5_N_A  TP-108  [TPSM70X135]  78.73 103.24 180 bottom
TX_D5_N_B  TP-108  [TPSM70X135]  78.73 33.28 0 bottom
TX_D5_P_A  TP-108  [TPSM70X135]  80 103.24 180 bottom
TX_D5_P_B  TP-108  [TPSM70X135]  80 33.28 0 bottom
TX_FRAME_N_A  TP-108  [TPSM70X135]  83.81 96.89 90 bottom
TX_FRAME_N_B  TP-108  [TPSM70X135]  83.81 26.93 270 bottom
TX_FRAME_P_A  TP-108  [TPSM70X135]  85.08 96.89 270 bottom
TX_FRAME_P_B  TP-108  [TPSM70X135]  85.08 26.93 270 bottom
U101  AD9361BBCZ  [BGA144]  25.34 113.49 45 bottom
U102  ADL5521ACPZ-R7  [QFN8_3X3_PAD1_75X1_45]  16.08 129.22 0 bottom
U103  ADL5521ACPZ-R7  [QFN8_3X3_PAD1_75X1_45]  9.76 123.38 90 bottom
U104  ADL5602ARKZ  [SOT-89]  48.77 123.37 0 bottom
U105  ADL5602ARKZ  [SOT-89]  9.08 93.47 270 bottom
U201  AD9361BBCZ  [BGA144]  24.94 26.15 135 bottom
U202  ADL5521ACPZ-R7  [QFN8_3X3_PAD1_75X1_45]  9.76 19.94 90 bottom
U203  ADL5521ACPZ-R7  [QFN8_3X3_PAD1_75X1_45]  15.6 9.78 180 bottom
U204  ADL5602ARKZ  [SOT-89]  15.51 47.56 90 bottom
U205  ADL5602ARKZ  [SOT-89]  44.14 8.26 0 bottom
U301  ADCLK846BCPZ  [QFN24_4X4_PAD2_3X2_3]  15.26 69.49 270 top
U302  ADF5355BCPZ  [QFN32_5X5_PAD3_5X3_5]  25.2 70.65 0 top
U303  M24C02-WDW6TP  [TSSOP8]  87.36 69.13 180 bottom
U304  AD7291BCPZ  [QFN20_4X4_PAD2_6X2_6]  36.94 47.51 0 top
U305  ADG918BRMZ  [MSOP8]  20.04 79.09 0 bottom
U306  ADG918BRMZ  [MSOP8]  19.96 62.02 180 bottom
U307  13617CF-S02QFN  [QFN16_3X3_PAD1_75X1_75]  34.88 70.13 180 top
U501  ADP2370ACPZ-R7  [QFN8_3X3_PAD2_44X1_7]  68.44 65.04 180 top
U502  ADM7150ARDZ-5.0  [SO8NB-PAD3_1X2_41]  60.8 56.74 270 top
U503  ADP2164ACPZ  [QFN16_4X4_PAD2_5X2_5]  66.58 83.53 180 top
U504  ADP1755ACPZ  [QFN16_4X4_PAD2_1X2_1]  52.03 80.82 90 top
U505  ADP1755ACPZ  [QFN16_4X4_PAD2_1X2_1]  52.02 74 90 top
U506  ADP1755ACPZ  [QFN16_4X4_PAD2_1X2_1]  52.05 60.41 90 top
U507  ADP1755ACPZ  [QFN16_4X4_PAD2_1X2_1]  52.06 67.22 90 top
U508  ADM7150ARDZ-3.3  [SO8NB-PAD3_1X2_41]  66.25 71.36 90 top
Y301  40MEGHz  [YSML126W98H47]  9.67 72.93 270 top

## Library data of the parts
C101 C102 C104 C116 C118 C120 C134 C147 C149 C201 C202 C204 C216 C218 C220 C234 C247 C249 = CAP: Tolerance: 10; User Part Number: UPN; alternate symbols: (C0402H22_ALT,C0201-2,C0402_A,C0402_ALT); part number: CAP_SM-1000PF,25V,10,E006762,C0201; tolerance: 10
C103 C105 C117 C152 C203 C205 C217 C252 C313 C510 C513 C516-C518 C521 C522 C525 C546 C549 C559 C568 C571 C573 C574 C584 C587 C588 C591 C592 C609 C612 C616 C629 C631 C633 C635 C636 C640 = CAP: User Part Number: UPN; Tolerance: 10; alternate symbols: (C0402H22_ALT,C0201-2,C0402_A,C0402_ALT); part number: CAP_SM-1UF,6.3V,10,E007449,C0402; tolerance: 10
C106-C111 C114 C115 C122-C133 C136 C137 C155 C156 C166 C206-C211 C214 C215 C222-C233 C236 C237 C255 C256 C266 C331 C332 C336-C339 C348-C353 C390 = CAP: Tolerance: 5; User Part Number: UPN; alternate symbols: (C0402H22_ALT,C0201-2,C0402_A,C0402_ALT); part number: CAP_SM-18PF,50V,5,E017960,C0201; tolerance: 5
C112 C153 C212 C253 C330 = CAP: User Part Number: UPN; Tolerance: 10; alternate symbols: (C0402H22_ALT,C0201-2,C0402_A,C0402_ALT); part number: CAP_SM-1200PF,50V,10,E012617,C0402; tolerance: 10
C113 C154 C213 C254 = CAP: User Part Number: UPN; Tolerance: 5; alternate symbols: (C0402H22_ALT,C0201-2,C0402_A,C0402_ALT); part number: CAP_SM-68PF,50V,5,E012591,C0402; tolerance: 5
C119 C121 C135 C219 C221 C235 C303 C306 C312 C314 C333 C340 C343 C346 C502 C503 C562 C563 C578 C579 C596 C597 C610 C614 C618 C622 C623 C638 = CAP: User Part Number: UPN; Tolerance: 20; alternate symbols: (C0402H22_ALT,C0201-2,C0402_A,C0402_ALT); part number: CAP_SM-10UF,6.3V,20,E007143,C0603; tolerance: 20
C138-C140 C142-C145 C148 C150 C162 C238-C240 C242-C245 C248 C250 C262 C301 C304 C305 C307 C308 C310 C311 C334 C335 C341 C342 C344 C345 C347 C501 C504 C505 C514 C551 C552 C555 C556 C560 C564-C567 C576 C580-C583 C594 C598 C599 C611 C615 C619 C620 C624-C627 C639 C650 = CAP: Tolerance: 10; User Part Number: UPN; alternate symbols: (C0402H22_ALT,C0201-2,C0402_A,C0402_ALT); part number: CAP_SM-0.1UF,6.3V,10,E011567,C0201; tolerance: 10
C146 C151 C246 C251 = CAP: User Part Number: UPN; Tolerance: 0.25pF; alternate symbols: (C0402H22_ALT,C0201-2,C0402_A,C0402_ALT); part number: CAP_SM-0.75PF,50V,0.25PF,E018456,C0402; tolerance: 0.25pF
C165 C265 = CAP: Tolerance: 5; User Part Number: UPN; alternate symbols: (C0402H22_ALT,C0201-2,C0402_A,C0402_ALT); part number: CAP_SM-39PF,25V,5,E018317,C0201; tolerance: 5
C302 C318 C319 C511 C512 C515 C519 C520 C523 C524 C545 C557 C558 C561 C569 C570 C572 C575 C577 C585 C586 C589 C590 C593 C595 C607 C608 C613 C617 C621 C628 C630 C632 C634 C637 C641 = CAP: Tolerance: 10; User Part Number: UPN; alternate symbols: (C0402H22_ALT,C0201-2,C0402_A,C0402_ALT); part number: CAP_SM-0.01UF,10V,10,E007201,C0201; tolerance: 10
C309 C320-C322 C326 C327 C531-C533 C535 C536 C541-C543 C547 C645 C646 C649 C651 C688 = CAP: User Part Number: UPN; Tolerance: 10; alternate symbols: (C0402H22_ALT,C0201-2,C0402_A,C0402_ALT); part number: CAP_SM-0.1UF,16V,10,E007200,C0402; tolerance: 10
C317 C538 C539 C544 C548 C643 C647 = CAP: User Part Number: UPN; Tolerance: 10; alternate symbols: (C0402H22_ALT,C0201-2,C0402_A,C0402_ALT); part number: CAP_SM-1UF,16V,10,E019219,C0402; tolerance: 10
C323-C325 = CAP: Tolerance: 10; User Part Number: UPN; alternate symbols: (C0402H22_ALT,C0201-2,C0402_A,C0402_ALT); part number: CAP_SM-10PF,10V,10,E007707,C0201-2; tolerance: 10
C328 = CAP: User Part Number: UPN; Tolerance: 10; alternate symbols: (C0402H22_ALT,C0201-2,C0402_A,C0402_ALT); part number: CAP_SM-2700PF,50V,10,E006649,C0402; tolerance: 10
C329 = CAP: User Part Number: UPN; Tolerance: 5; alternate symbols: (C0402H22_ALT,C0201-2,C0402_A,C0402_ALT); part number: CAP_SM-39000PF,10V,5,E012589,C0402; tolerance: 5
C530 C534 C537 C540 C642 C644 C648 = CAP: Tolerance: 20; User Part Number: UPN; alternate symbols: (C0402H22_ALT,C0201-2,C0402_A,C0402_ALT); part number: CAP_SM-10UF,16V,20,E018424,C1206H71; tolerance: 20
C550 C553 C554 = CAP: Tolerance: 10; User Part Number: UPN; alternate symbols: (C0402H22_ALT,C0201-2,C0402_A,C0402_ALT); part number: CAP_SM-47UF,6.3V,10,E008247,C0805H60; tolerance: 10
CAL_SW_1-CAL_SW_4 DATA_CLK_N_A DATA_CLK_N_B DATA_CLK_P_A DATA_CLK_P_B DEBUG_1-DEBUG_4 FB_CLK_N_A FB_CLK_N_B FB_CLK_P_A FB_CLK_P_B REF_CLK_FMC_N REF_CLK_FMC_P RX_D0_N_A RX_D0_N_B RX_D0_P_A RX_D0_P_B RX_D1_N_A RX_D1_N_B RX_D1_P_A RX_D1_P_B RX_D2_N_A RX_D2_N_B RX_D2_P_A RX_D2_P_B RX_D3_N_A RX_D3_N_B RX_D3_P_A RX_D3_P_B RX_D4_N_A RX_D4_N_B RX_D4_P_A RX_D4_P_B RX_D5_N_A RX_D5_N_B RX_D5_P_A RX_D5_P_B RX_FRAME_N_A RX_FRAME_N_B RX_FRAME_P_A RX_FRAME_P_B SPI_CLK SPI_DI SPI_DO SPI_ENB_A SPI_ENB_B TX_D0_N_A TX_D0_N_B TX_D0_P_A TX_D0_P_B TX_D1_N_A TX_D1_N_B TX_D1_P_A TX_D1_P_B TX_D2_N_A TX_D2_N_B TX_D2_P_A TX_D2_P_B TX_D3_N_A TX_D3_N_B TX_D3_P_A TX_D3_P_B TX_D4_N_A TX_D4_N_B TX_D4_P_A TX_D4_P_B TX_D5_N_A TX_D5_N_B TX_D5_P_A TX_D5_P_B TX_FRAME_N_A TX_FRAME_N_B TX_FRAME_P_A TX_FRAME_P_B = CNTP1P: User Part Number: UPN; alternate symbols: (CNBANANA_ALT); part number: CNTP1P_SM-TP-108,E000956,TPSM70X135
DS301 = DIOLED: Tolerance: N/A; User Part Number: UPN; part number: DIOLED_SM-LTST-C190GKT,2.1V,N/A,E006239,LED0603; tolerance: N/A
E1 E501 E503 E507 E509 E511-E515 = FERRITE: User Part Number: UPN; Tolerance: 25; part number: FERRITE_SM-75OHM,25,E017348,L0402; tolerance: 25
E504 E510 = FERRITE: User Part Number: UPN; Tolerance: N/A; part number: FERRITE_SM-39OHM,N/A,E002359,L0805; tolerance: N/A
FL100-FL103 FL200-FL203 = FLTRBP4P_V2: User Part Number: UPN; part number: FLTRBP4P_V2_SM-2400-2500MEGHZ,E020674,FL0603
J101-J104 J110-J113 J201-J204 J210-J213 J301 = CNBNC5P: User Part Number: UPN; alternate symbols: (CNAMPHENOL132255-11_ALT); part number: CNBNC5P_SM-JOHNSON142-0701-851,E000923,CNJOHNSON142-0701-851
J302 = CNBNC5P: User Part Number: UPN; alternate symbols: (CNAMPHENOL132255-11_ALT); part number: CNBNC5P_TH-142-0701-201,E000916,CNJOHNSON142-0701-201
L101-L105 L107 L201-L205 L207 = IND: Tolerance: 5; User Part Number: UPN; alternate symbols: (L0402-2,L0603_ALT); part number: IND_SM-330NH,5,E006599,L0805-F; tolerance: 5
L106 L108 L206 L208 = IND: Tolerance: 5; User Part Number: UPN; alternate symbols: (L0402-2,L0603_ALT); part number: IND_SM-1NH,5,E007654,L0402-2; tolerance: 5
L110 L111 L210 L211 = IND: Tolerance: 2; User Part Number: UPN; alternate symbols: (L0402-2,L0603_ALT); part number: IND_SM-43NH,2,E018234,L7144A; tolerance: 2
L501 = IND: User Part Number: UPN; Tolerance: 30; alternate symbols: (L0402-2,L0603_ALT); part number: IND_SM-0.47UH,30,E018627,L1210H67; tolerance: 30
L502 = IND: User Part Number: UPN; Tolerance: 20; alternate symbols: (L0402-2,L0603_ALT); part number: IND_SM-22UH,20,E020360,LSMSQ189H123; tolerance: 20
L503 = IND: User Part Number: UPN; Tolerance: 20; alternate symbols: (L0402-2,L0603_ALT); part number: IND_SM-2.2UH,20,E016651,LSMSQ157H83; tolerance: 20
NOREF#14 NOREF#16-NOREF#19 = -: Tolerance: TOL; User Part Number: UPN
P101 P201 = CN26P: User Part Number: UPN; part number: CN26P_TH-TSW-113-23-L-D,E010298,CNSAMTECTSW-113-23-L-D-ST
P401 P402 = CN160P_CDGH: User Part Number: UPN; part number: CN160P_CDGH_SM-ASP-134604-01,E011383,CNSAMTECASP-134604-01
P501 = CN3P: User Part Number: UPN; part number: CN3P_TH-SAMTECTSW10608GS3PIN,E000812,CNBERG1X3H205LD36
R101 R102 R201 R202 R301 R317 R318 R335 R350 R404 = RES: Tolerance: 1; User Part Number: UPN; alternate symbols: (RRAD984L1500W75H520LD32;TO220H590_ALT;R0402_A;R0603_A,R0402_ALT); part number: RES_SM-49.9,E007693,1/20W,1,R0201; tolerance: 1
R103-R107 R111 R203-R207 R211 R303-R305 R310 R319 R320 R325-R327 R351 R403 R405-R407 R504 R505 R507 R509 R511 R513 R515 R517 R519 R521 = RES: Tolerance: 1; User Part Number: UPN; alternate symbols: (RRAD984L1500W75H520LD32;TO220H590_ALT;R0402_A;R0603_A,R0402_ALT); part number: RES_SM-10K,E004011,1/20W,1,R0201; tolerance: 1
R108 R110 R208 R210 = RES: Tolerance: 1; User Part Number: UPN; alternate symbols: (RRAD984L1500W75H520LD32;TO220H590_ALT;R0402_A;R0603_A,R0402_ALT); part number: RES_SM-1.3K,E015613,1/10W,1,R0402; tolerance: 1
R109 R112 R209 R212 = RES: Tolerance: 5; User Part Number: UPN; alternate symbols: (RRAD984L1500W75H520LD32;TO220H590_ALT;R0402_A;R0603_A,R0402_ALT); part number: RES_SM-0,E003438,1/16W,5,R0402; tolerance: 5
R121 R122 R221 R222 R523 = RES: Tolerance: 1; User Part Number: UPN; alternate symbols: (RRAD984L1500W75H520LD32;TO220H590_ALT;R0402_A;R0603_A,R0402_ALT); part number: RES_SM-10,E013982,1/20W,1,R0201; tolerance: 1
R123 R124 R223 R224 = RES: User Part Number: UPN; alternate symbols: (RRAD984L1500W75H520LD32;TO220H590_ALT;R0402_A;R0603_A,R0402_ALT); part number: RES_SM-1,E014056,1/20W,1,R0201
R125 R225 = RES: Tolerance: 1; User Part Number: UPN; alternate symbols: (RRAD984L1500W75H520LD32;TO220H590_ALT;R0402_A;R0603_A,R0402_ALT); part number: RES_SM-14.3K,E014068,1/20W,1,R0201; tolerance: 1
R302 = RES: User Part Number: UPN; Tolerance: 1; alternate symbols: (RRAD984L1500W75H520LD32;TO220H590_ALT;R0402_A;R0603_A,R0402_ALT); part number: RES_SM-237,E010703,1/10W,1,R0603; tolerance: 1
R306-R308 R312-R314 R328 R329 R508 R512 R516 R520 = RES: Tolerance: 1; User Part Number: UPN; alternate symbols: (RRAD984L1500W75H520LD32;TO220H590_ALT;R0402_A;R0603_A,R0402_ALT); part number: RES_SM-16K,E019648,1/20W,1,R0201; tolerance: 1
R309 R506 = RES: Tolerance: 1; User Part Number: UPN; alternate symbols: (RRAD984L1500W75H520LD32;TO220H590_ALT;R0402_A;R0603_A,R0402_ALT); part number: RES_SM-20K,E004013,1/20W,1,R0201; tolerance: 1
R315 = RES: Tolerance: 5; User Part Number: UPN; alternate symbols: (RRAD984L1500W75H520LD32;TO220H590_ALT;R0402_A;R0603_A,R0402_ALT); part number: RES_SM-360,E003457,1/16W,5,R0402; tolerance: 5
R316 = RES: Tolerance: 1; User Part Number: UPN; alternate symbols: (RRAD984L1500W75H520LD32;TO220H590_ALT;R0402_A;R0603_A,R0402_ALT); part number: RES_SM-680,E015602,1/10W,1,R0402; tolerance: 1
R323 = RES: Tolerance: 1; User Part Number: UPN; alternate symbols: (RRAD984L1500W75H520LD32;TO220H590_ALT;R0402_A;R0603_A,R0402_ALT); part number: RES_SM-4.7K,E008190,1/16W,1,R0402; tolerance: 1
R360 = RES: Tolerance: 5; User Part Number: UPN; alternate symbols: (RRAD984L1500W75H520LD32;TO220H590_ALT;R0402_A;R0603_A,R0402_ALT); part number: RES_SM-0,E004015,1/20W,5,R0201; tolerance: 5
R401 R402 = RES: Tolerance: 1; User Part Number: UPN; alternate symbols: (RRAD984L1500W75H520LD32;TO220H590_ALT;R0402_A;R0603_A,R0402_ALT); part number: RES_SM-2K,E007220,1/20W,1,R0201; tolerance: 1
R501 = RES: Tolerance: 1; User Part Number: UPN; alternate symbols: (RRAD984L1500W75H520LD32;TO220H590_ALT;R0402_A;R0603_A,R0402_ALT); part number: RES_SM-36K,E018748,1/16W,1,R0402; tolerance: 1
R502 = RES: Tolerance: 1; User Part Number: UPN; alternate symbols: (RRAD984L1500W75H520LD32;TO220H590_ALT;R0402_A;R0603_A,R0402_ALT); part number: RES_SM-232K,E006802,1/16W,1,R0402; tolerance: 1
R510 R514 R518 R522 = RES: User Part Number: UPN; alternate symbols: (RRAD984L1500W75H520LD32;TO220H590_ALT;R0402_A;R0603_A,R0402_ALT); part number: RES_SM-0,E004448,1/4W,0,R1206
T101 T102 T201 T202 = XFMR3600BL: User Part Number: UPN; alternate symbols: (XFMR2012); part number: XFMR3600BL_SM-2450BL15B050E,E011951,XFMR2450BL15B050
T103-T108 T203-T208 = XFMRTCMXXXX_V3: User Part Number: UPN; part number: XFMRTCMXXXX_V3_SM-TCM1-63AX+,E018203,TSML150W160H160
TP302 TP303 TP306 TP307 = NCWP: User Part Number: UPN; part number: NCWP_TH-WP45,E002516,TPC75D45
U101 U201 = AD9361: User Part Number: UPN; part number: AD9361_SM-AD9361BBCZ,E011827,BGA144
U102 U103 U202 U203 = ADL5521_PRELIM: User Part Number: UPN; part number: ADL5521_PRELIM_SM-ADL5521ACPZ-R7,E007971,QFN8_3X3_PAD1_75X1_45
U104 U105 U204 U205 = ADL5320: User Part Number: UPN; part number: ADL5320_SM-ADL5602ARKZ,E014601,SOT-89
U301 = ADCLK846: User Part Number: UPN; part number: ADCLK846_SM-ADCLK846BCPZ,E013778,QFN24_4X4_PAD2_3X2_3
U302 = ADF5355: User Part Number: UPN; part number: ADF5355_SM-ADF5355BCPZ,E019999,QFN32_5X5_PAD3_5X3_5
U303 = ICM24CXX: User Part Number: UPN; part number: ICM24CXX_SM-M24C02-WDW6TP,E017713,TSSOP8
U304 = AD7291: User Part Number: UPN; part number: AD7291_SM-AD7291BCPZ,E017361,QFN20_4X4_PAD2_6X2_6
U305 U306 = ADG91X: User Part Number: UPN; part number: ADG91X_SM-ADG918BRMZ,E013109,MSOP8
U307 = IC13617CF: User Part Number: UPN; part number: IC13617CF_SM-13617CF-S02QFN,E020388,QFN16_3X3_PAD1_75X1_75
U501 = ADP237X: User Part Number: UPN; part number: ADP237X_SM-ADP2370ACPZ-R7,E016641,QFN8_3X3_PAD2_44X1_7
U502 = ADM7150: User Part Number: UPN; part number: ADM7150_SM-ADM7150ARDZ-5.0,E016814,SO8NB-PAD3_1X2_41
U503 = ADP2164: User Part Number: UPN; part number: ADP2164_SM-ADP2164ACPZ,E013699,QFN16_4X4_PAD2_5X2_5
U504-U507 = ADP1755: User Part Number: UPN; part number: ADP1755_SM-ADP1755ACPZ,E012964,QFN16_4X4_PAD2_1X2_1
U508 = ADM7150: User Part Number: UPN; part number: ADM7150_SM-ADM7150ARDZ-3.3,E018052,SO8NB-PAD3_1X2_41
Y301 = XTALOSC4P_V21: User Part Number: UPN; part number: XTALOSC4P_V21_SM-40MEGHZ,E020493,YSML126W98H47

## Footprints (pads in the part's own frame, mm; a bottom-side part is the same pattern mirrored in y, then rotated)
BGA144
  round 0.356 smd: A1(-4.4,-4.4) A2(-4.4,-3.6) A3(-4.4,-2.8) A4(-4.4,-2) A5(-4.4,-1.2) A6(-4.4,-0.4) A7(-4.4,0.4) A8(-4.4,1.2) A9(-4.4,2) A10(-4.4,2.8) A11(-4.4,3.6) A12(-4.4,4.4) B1(-3.6,-4.4) B2(-3.6,-3.6) B3(-3.6,-2.8) B4(-3.6,-2) B5(-3.6,-1.2) B6(-3.6,-0.4) B7(-3.6,0.4) B8(-3.6,1.2) B9(-3.6,2) B10(-3.6,2.8) B11(-3.6,3.6) B12(-3.6,4.4) C1(-2.8,-4.4) C2(-2.8,-3.6) C3(-2.8,-2.8) C4(-2.8,-2) C5(-2.8,-1.2) C6(-2.8,-0.4) C7(-2.8,0.4) C8(-2.8,1.2) C9(-2.8,2) C10(-2.8,2.8) C11(-2.8,3.6) C12(-2.8,4.4) D1(-2,-4.4) D2(-2,-3.6) D3(-2,-2.8) D4(-2,-2) D5(-2,-1.2) D6(-2,-0.4) D7(-2,0.4) D8(-2,1.2) D9(-2,2) D10(-2,2.8) D11(-2,3.6) D12(-2,4.4) E1(-1.2,-4.4) E2(-1.2,-3.6) E3(-1.2,-2.8) E4(-1.2,-2) E5(-1.2,-1.2) E6(-1.2,-0.4) E7(-1.2,0.4) E8(-1.2,1.2) E9(-1.2,2) E10(-1.2,2.8) E11(-1.2,3.6) E12(-1.2,4.4) F1(-0.4,-4.4) F2(-0.4,-3.6) F3(-0.4,-2.8) F4(-0.4,-2) F5(-0.4,-1.2) F6(-0.4,-0.4) F7(-0.4,0.4) F8(-0.4,1.2) F9(-0.4,2) F10(-0.4,2.8) F11(-0.4,3.6) F12(-0.4,4.4) G1(0.4,-4.4) G2(0.4,-3.6) G3(0.4,-2.8) G4(0.4,-2) G5(0.4,-1.2) G6(0.4,-0.4) G7(0.4,0.4) G8(0.4,1.2) G9(0.4,2) G10(0.4,2.8) G11(0.4,3.6) G12(0.4,4.4) H1(1.2,-4.4) H2(1.2,-3.6) H3(1.2,-2.8) H4(1.2,-2) H5(1.2,-1.2) H6(1.2,-0.4) H7(1.2,0.4) H8(1.2,1.2) H9(1.2,2) H10(1.2,2.8) H11(1.2,3.6) H12(1.2,4.4) J1(2,-4.4) J2(2,-3.6) J3(2,-2.8) J4(2,-2) J5(2,-1.2) J6(2,-0.4) J7(2,0.4) J8(2,1.2) J9(2,2) J10(2,2.8) J11(2,3.6) J12(2,4.4) K1(2.8,-4.4) K2(2.8,-3.6) K3(2.8,-2.8) K4(2.8,-2) K5(2.8,-1.2) K6(2.8,-0.4) K7(2.8,0.4) K8(2.8,1.2) K9(2.8,2) K10(2.8,2.8) K11(2.8,3.6) K12(2.8,4.4) L1(3.6,-4.4) L2(3.6,-3.6) L3(3.6,-2.8) L4(3.6,-2) L5(3.6,-1.2) L6(3.6,-0.4) L7(3.6,0.4) L8(3.6,1.2) L9(3.6,2) L10(3.6,2.8) L11(3.6,3.6) L12(3.6,4.4) M1(4.4,-4.4) M2(4.4,-3.6) M3(4.4,-2.8) M4(4.4,-2) M5(4.4,-1.2) M6(4.4,-0.4) M7(4.4,0.4) M8(4.4,1.2) M9(4.4,2) M10(4.4,2.8) M11(4.4,3.6) M12(4.4,4.4)
C0201
  rect 0.356x0.356 smd: 1(-0.305,0) 2(0.305,0)
C0201-2
  rect 0.254x0.33 smd: 1(-0.254,0) 2(0.254,0)
C0402
  rect 0.699x0.635 smd: 1(-0.54,0) 2(0.54,0)
C0603
  rect 0.978x0.889 smd: 1(-0.819,0) 2(0.819,0)
C0805H60
  rect 1.295x1.6 smd: 1(-0.953,0) 2(0.953,0)
C1206H71
  rect 1.6x2.007 smd: 1(-1.397,0) 2(1.397,0)
CNBERG1X3H205LD36
  rect 1.651x1.651 hole 1.016: 1(0,0)
  round 1.651 hole 1.016: 2(2.54,0) 3(5.08,0)
CNJOHNSON142-0701-201
  round 2.032 hole 1.524: 1(0,0) 2(-2.54,2.54) 3(2.54,2.54) 4(2.54,-2.54) 5(-2.54,-2.54)
CNJOHNSON142-0701-851
  rect 2.54x0.432 smd: 1(-0.508,0)
  rect 6.35x1.524 hole 0.508: 2(-2.413,4.191) 4(-2.413,-4.191)
  round 0.305 smd: 3(-2.413,4.191) 5(-2.413,-4.191)
CNSAMTECASP-134604-01
  round 2.54 hole 1.27 unplated: (-27.178,0) (27.178,3.048)
  round 0.635 smd: C1(-24.765,-3.175) C2(-23.495,-3.175) C3(-22.225,-3.175) C4(-20.955,-3.175) C5(-19.685,-3.175) C6(-18.415,-3.175) C7(-17.145,-3.175) C8(-15.875,-3.175) C9(-14.605,-3.175) C10(-13.335,-3.175) C11(-12.065,-3.175) C12(-10.795,-3.175) C13(-9.525,-3.175) C14(-8.255,-3.175) C15(-6.985,-3.175) C16(-5.715,-3.175) C17(-4.445,-3.175) C18(-3.175,-3.175) C19(-1.905,-3.175) C20(-0.635,-3.175) C21(0.635,-3.175) C22(1.905,-3.175) C23(3.175,-3.175) C24(4.445,-3.175) C25(5.715,-3.175) C26(6.985,-3.175) C27(8.255,-3.175) C28(9.525,-3.175) C29(10.795,-3.175) C30(12.065,-3.175) C31(13.335,-3.175) C32(14.605,-3.175) C33(15.875,-3.175) C34(17.145,-3.175) C35(18.415,-3.175) C36(19.685,-3.175) C37(20.955,-3.175) C38(22.225,-3.175) C39(23.495,-3.175) C40(24.765,-3.175) D1(-24.765,-1.905) D2(-23.495,-1.905) D3(-22.225,-1.905) D4(-20.955,-1.905) D5(-19.685,-1.905) D6(-18.415,-1.905) D7(-17.145,-1.905) D8(-15.875,-1.905) D9(-14.605,-1.905) D10(-13.335,-1.905) D11(-12.065,-1.905) D12(-10.795,-1.905) D13(-9.525,-1.905) D14(-8.255,-1.905) D15(-6.985,-1.905) D16(-5.715,-1.905) D17(-4.445,-1.905) D18(-3.175,-1.905) D19(-1.905,-1.905) D20(-0.635,-1.905) D21(0.635,-1.905) D22(1.905,-1.905) D23(3.175,-1.905) D24(4.445,-1.905) D25(5.715,-1.905) D26(6.985,-1.905) D27(8.255,-1.905) D28(9.525,-1.905) D29(10.795,-1.905) D30(12.065,-1.905) D31(13.335,-1.905) D32(14.605,-1.905) D33(15.875,-1.905) D34(17.145,-1.905) D35(18.415,-1.905) D36(19.685,-1.905) D37(20.955,-1.905) D38(22.225,-1.905) D39(23.495,-1.905) D40(24.765,-1.905) G1(-24.765,1.905) G2(-23.495,1.905) G3(-22.225,1.905) G4(-20.955,1.905) G5(-19.685,1.905) G6(-18.415,1.905) G7(-17.145,1.905) G8(-15.875,1.905) G9(-14.605,1.905) G10(-13.335,1.905) G11(-12.065,1.905) G12(-10.795,1.905) G13(-9.525,1.905) G14(-8.255,1.905) G15(-6.985,1.905) G16(-5.715,1.905) G17(-4.445,1.905) G18(-3.175,1.905) G19(-1.905,1.905) G20(-0.635,1.905) G21(0.635,1.905) G22(1.905,1.905) G23(3.175,1.905) G24(4.445,1.905) G25(5.715,1.905) G26(6.985,1.905) G27(8.255,1.905) G28(9.525,1.905) G29(10.795,1.905) G30(12.065,1.905) G31(13.335,1.905) G32(14.605,1.905) G33(15.875,1.905) G34(17.145,1.905) G35(18.415,1.905) G36(19.685,1.905) G37(20.955,1.905) G38(22.225,1.905) G39(23.495,1.905) G40(24.765,1.905) H1(-24.765,3.175) H2(-23.495,3.175) H3(-22.225,3.175) H4(-20.955,3.175) H5(-19.685,3.175) H6(-18.415,3.175) H7(-17.145,3.175) H8(-15.875,3.175) H9(-14.605,3.175) H10(-13.335,3.175) H11(-12.065,3.175) H12(-10.795,3.175) H13(-9.525,3.175) H14(-8.255,3.175) H15(-6.985,3.175) H16(-5.715,3.175) H17(-4.445,3.175) H18(-3.175,3.175) H19(-1.905,3.175) H20(-0.635,3.175) H21(0.635,3.175) H22(1.905,3.175) H23(3.175,3.175) H24(4.445,3.175) H25(5.715,3.175) H26(6.985,3.175) H27(8.255,3.175) H28(9.525,3.175) H29(10.795,3.175) H30(12.065,3.175) H31(13.335,3.175) H32(14.605,3.175) H33(15.875,3.175) H34(17.145,3.175) H35(18.415,3.175) H36(19.685,3.175) H37(20.955,3.175) H38(22.225,3.175) H39(23.495,3.175) H40(24.765,3.175)
CNSAMTECTSW-113-23-L-D-ST
  rect 1.651x1.651 hole 1.143: 1(0,0)
  round 1.651 hole 1.143: 2(0,2.54) 3(2.54,0) 4(2.54,2.54) 5(5.08,0) 6(5.08,2.54) 7(7.62,0) 8(7.62,2.54) 9(10.16,0) 10(10.16,2.54) 11(12.7,0) 12(12.7,2.54) 13(15.24,0) 14(15.24,2.54) 15(17.78,0) 16(17.78,2.54) 17(20.32,0) 18(20.32,2.54) 19(22.86,0) 20(22.86,2.54) 21(25.4,0) 22(25.4,2.54) 23(27.94,0) 24(27.94,2.54) 25(30.48,0) 26(30.48,2.54)
